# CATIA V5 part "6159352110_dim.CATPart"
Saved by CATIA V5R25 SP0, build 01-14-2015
Part number: 6159352110_dim
Source: made
Property "PROI_CREATED_ON": "12/17/2008 9:21:37 AM"
Property "BLANK_DRAWING": "--"
Property "DRAWN_BY": "FPA"
Property "FINISH": "--"
Property "HEAT_TREATMENT": "ASSIGN"
Property "MATERIAL": "ASSIGN"
Property "PROJECT": "--"
Property "PROTOTYPE_NO": "--"
Property "RELATED_DRAWING": "--"
Property "COMPLETE_MATERIAL": "ASSIGN-ASSIGN"
Property "DESCRIPTION": "Q-SHIELD 150-S"
Property "DRAWING_EXIST": "--"
Property "MANUFACTURER": "--"
Property "MANUFACTURER_2": "--"
Property "MANUFACTURER_REF": "--"
Property "TYPE_PART": "--"
Property "TODAY_DATE": "2021/06/10"
Property "PDMREV": "01.0"
Property "PDMRL": "Production"
Property "PROI_REVISION": "01"
Property "PROI_VERSION": "0"
Property "PROI_RELEASE": "Production"
Property "PTC_MODIFIED": false
Property "MFG_WP_MATERIAL": "ASSIGN"
Property "COMPANY_CODE": "---"
Property "DESCRIPTION_JP": "--"
Property "PQP_DOCUMENT": "--"
Property "GHOST": false
Property "NO_PART": false
Property "PTC_WM_ITERATION": "0"
Property "PTC_WM_VERSION": "01.0"
Property "PTC_WM_CREATED_ON": "10-Jun-21 09:25:52 AM"
Property "PTC_WM_MODIFIED_ON": "10-Jun-21 03:21:17 PM"
Property "PTC_WM_NAME": "6159352110_dim.prt"
Property "PTC_WM_NUMBER": "6159352110_DIM.PRT"
Property "PTC_WM_LIFECYCLE_STATE": "Production"
Property "PTC_WM_LIFECYCLE": "Design_Process"
Property "PTC_WM_REVISION": "01"
Property "PTC_WM_CREATED_BY": "Florian Pavageau (Grefpav) (Grefpav: CPD)"
Property "PTC_WM_MODIFIED_BY": "Florian Pavageau (Grefpav) (Grefpav: CPD)"
Property "PTC_ORGANIZATION_ID": "CPD"
Property "PTC_WM_LOCATION": "/Products/TORQUE MEASUREMENT SYSTEMS/A2010 - DELTAWRENCH GEN2/9-01-Dimensional D"
Property "PTC_WM_PART_NAME": "6159352110_dim.prt"
Property "PTC_WM_PART_NUMBER": "6159352110_DIM"
Property "PTC_WM_TEAM": "Default"
Property "EXPORT_CONTROL": "NULL"
Property "PTC_COMMON_NAME": "6159352110_dim.prt"
Property "PTC_MASTER_MATERIAL": "ASSIGN"
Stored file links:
  d:\ptc\Echange\temp\6159352110_dim.CATPart

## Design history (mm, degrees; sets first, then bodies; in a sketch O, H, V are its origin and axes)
AxisSystem1 "CS0": origin (0, 0, 0), X (1, 0, 0), Y (0, 1, 0), Z (0, 0, 1)
Set1
  DatumSurface1 "Sheet.1"
  DatumSurface2 "Sheet.2"
  DatumSurface3 "Sheet.3"
  DatumSurface4 "Sheet.4"
  DatumSurface5 "Sheet.5"
  DatumSurface6 "Sheet.6"
  DatumSurface7 "Sheet.7"
  DatumSurface8 "Sheet.8"
  DatumSurface9 "Sheet.9"
  Plane1 "RIGHT": stored without definition
  Plane2 "TOP": stored without definition
  Plane3 "FRONT": stored without definition
Body1 "PartBody" (main body)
